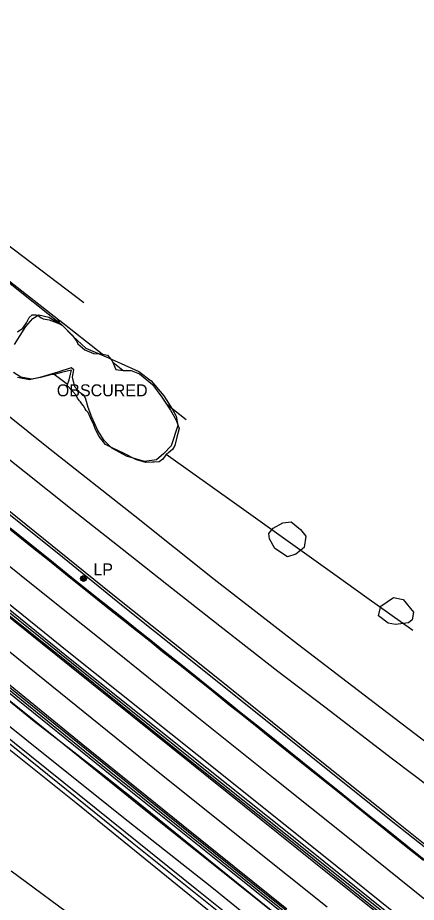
# Model space of a CAD drawing. Extents: x 368532 to 392481, y 10654822 to 10676899.
# Drawn here: x 380004 to 380170.4, y 10659071.4 to 10659440.6 of the extents above; entities that cross this region are included whole.
import ezdxf

# ---------------------------------------------------------------- set-up
doc = ezdxf.new("R2010")
doc.units = 0
for name, color, linetype in [('p_dtm obscured area', 7, 'Continuous'), ('p_dtm retaining wall', 7, 'Continuous'), ('p_dtm sidewalk', 7, 'Continuous'), ('p_railroad rr control', 7, 'Continuous'), ('p_road - paved curb', 7, 'Continuous'), ('p_road conc barrier', 7, 'Continuous'), ('p_road dirt road', 7, 'Continuous'), ('p_road paint stripe', 7, 'Continuous'), ('p_structure fence', 7, 'Continuous'), ('p_structure unidentified', 7, 'Continuous'), ('p_structure wall', 7, 'Continuous'), ('p_utility general pole', 7, 'Continuous'), ('p_veg woods', 7, 'Continuous')]:
    doc.layers.add(name, color=color, linetype=linetype)

msp = doc.modelspace()

# ---------------------------------------------------------------- linework, layer by layer
at = {"layer": 'p_dtm obscured area'}
msp.add_lwpolyline([(380003.9, 10659309.42), (380006.21, 10659311), (380007.68, 10659313.15), (380008.76, 10659315.44), (380010.11, 10659316.61), (380011.54, 10659316.5), (380012.48, 10659316.24), (380013.85, 10659315.31), (380014.65, 10659314.9), (380017.07, 10659314.49), (380022.3, 10659312.48), (380026.76, 10659308.06), (380028.69, 10659305.43), (380029.08, 10659304.42), (380032.07, 10659301.99), (380035.6, 10659300.46), (380038.86, 10659300.22), (380041.52, 10659299.67), (380043.38, 10659297.39), (380044.98, 10659293.77), (380048.01, 10659293.36), (380051.4, 10659293.33), (380054.9, 10659291.95), (380060.2, 10659287.46), (380064.15, 10659282.13), (380067.83, 10659276.72), (380070.15, 10659272.54), (380071.35, 10659269.17), (380070.41, 10659265.56), (380069.53, 10659261.97), (380068.56, 10659260.32), (380066.97, 10659258.91), (380066.03, 10659258.35), (380065.8, 10659258.06), (380064.62, 10659256.38), (380063.07, 10659255.16), (380060.96, 10659255.03), (380060.25, 10659255.01), (380057.43, 10659254.94), (380053.58, 10659256.02), (380048.12, 10659258.86), (380043.76, 10659260.9), (380040.67, 10659262.47), (380038.02, 10659265.83), (380036.42, 10659268.69), (380035.75, 10659270.63), (380034.43, 10659273.58), (380033.39, 10659275.83), (380032.54, 10659276.69), (380032.1, 10659277.38), (380031.41, 10659278.63), (380031.36, 10659278.76), (380030.83, 10659279.47), (380030.17, 10659280.24), (380029.74, 10659280.65), (380028.93, 10659281.82), (380028.4, 10659283.07), (380026.82, 10659284.66), (380024.59, 10659287.1), (380024.72, 10659287.44), (380025.55, 10659289.44), (380026.04, 10659291.76), (380026.42, 10659293.47), (380022.23, 10659292.42), (380019.16, 10659291.63), (380018.28, 10659291.61), (380013.57, 10659290.38), (380009.88, 10659289.76), (380005.29, 10659290.55), (380002.2, 10659292.5)], dxfattribs=at)
at = {"layer": 'p_dtm retaining wall'}
for p, q in [((380024.72, 10659287.44), (380019.16, 10659291.63)), ((380066.03, 10659258.35), (380067, 10659257.64)), ((380067, 10659257.64), (380094.51, 10659238.03)), ((380094.51, 10659238.03), (380109.11, 10659227.62)), ((380109.11, 10659227.62), (380136.42, 10659208.16)), ((380136.42, 10659208.16), (380149.79, 10659198.63)), ((380149.79, 10659198.63), (380168.95, 10659184.97)), ((379972.88, 10659177.76), (380010.92, 10659146.96)), ((380010.92, 10659146.96), (380026.16, 10659135.07)), ((380026.16, 10659135.07), (380041.32, 10659123.24)), ((380041.32, 10659123.24), (380052.12, 10659114.81)), ((380052.12, 10659114.81), (380084.53, 10659088.47)), ((380084.53, 10659088.47), (380133.86, 10659048.76))]:
    msp.add_line(p, q, dxfattribs=at)
at = {"layer": 'p_dtm sidewalk'}
for p, q in [((380020.43, 10659217.2), (379986.54, 10659244.35)), ((380048.04, 10659194.88), (380020.43, 10659217.2)), ((380086.6, 10659164.09), (380048.04, 10659194.88)), ((379965.55, 10659186.98), (380004.03, 10659155.88)), ((380124.3, 10659133.86), (380086.6, 10659164.09)), ((380004.03, 10659155.88), (380049.88, 10659118.84)), ((380159.15, 10659105.98), (380124.3, 10659133.86)), ((380049.88, 10659118.84), (380092.25, 10659084.87)), ((380191.31, 10659080.51), (380159.15, 10659105.98)), ((380092.25, 10659084.87), (380135.23, 10659050.48))]:
    msp.add_line(p, q, dxfattribs=at)
at = {"layer": 'p_railroad rr control'}
for points in [[(380031.65, 10659321.51), (379994.98, 10659349.29), (379961.61, 10659374.9), (379923.84, 10659403.98), (379885.83, 10659432.99), (379850.89, 10659459.72), (379817.07, 10659485.91), (379781.97, 10659514.51), (379763.8, 10659529.78), (379746.44, 10659544.62), (379721.67, 10659567.15), (379695.43, 10659591.4), (379678.11, 10659608.03), (379656.11, 10659629.71), (379630.45, 10659654.81), (379614.94, 10659670.07)], [(379982.8, 10659288.36), (380016.9, 10659261), (380052.84, 10659232.61), (380085.94, 10659206.26), (380120.72, 10659179.3), (380153.32, 10659154.27), (380191.45, 10659125.29), (380231.37, 10659095.21), (380261.57, 10659072.75), (380294.45, 10659048.57), (380330.85, 10659022.17), (380360.99, 10659000.26)], [(380347.38, 10658976.44), (380320.5, 10658997.04), (380307.32, 10659007.82), (380293.12, 10659020.18), (380275.57, 10659035.91), (380257.07, 10659052.87), (380239.39, 10659068.32), (380225.36, 10659080.48), (380211.07, 10659092.38), (380190.43, 10659108.38), (380160.49, 10659131.03), (380132.22, 10659152.81), (380112.56, 10659167.73), (380088.41, 10659186.61), (380066.31, 10659204.03), (380047.58, 10659218.72), (380026.77, 10659235.12), (380006.83, 10659250.97), (379987.69, 10659266.12), (379971.34, 10659279.52)]]:
    msp.add_lwpolyline(points, dxfattribs=at)
at = {"layer": 'p_road - paved curb'}
for p, q in [((380010.89, 10659219.06), (380000.68, 10659227.28)), ((380011.11, 10659219.33), (380000.9, 10659227.55)), ((380016.5, 10659214.61), (380010.89, 10659219.06)), ((380016.72, 10659214.88), (380011.11, 10659219.33)), ((380023.61, 10659172.45), (379971.64, 10659213.83)), ((379977.66, 10659211.92), (380025.93, 10659173.01)), ((380026.26, 10659206.65), (380016.5, 10659214.61)), ((380026.48, 10659206.92), (380016.72, 10659214.88)), ((380037.43, 10659197.77), (380026.26, 10659206.65)), ((380037.65, 10659198.04), (380026.48, 10659206.92)), ((380042.47, 10659193.73), (380037.43, 10659197.77)), ((380042.69, 10659194), (380037.65, 10659198.04)), ((380048.29, 10659189.07), (380042.47, 10659193.73)), ((380048.51, 10659189.34), (380042.69, 10659194)), ((379962.31, 10659192.11), (380009.44, 10659153.87)), ((380053.89, 10659185.06), (380048.51, 10659189.34)), ((380053.67, 10659184.79), (380048.29, 10659189.07)), ((380059.37, 10659180.3), (380053.67, 10659184.79)), ((380059.59, 10659180.57), (380053.89, 10659185.06)), ((380064.58, 10659176.08), (380059.37, 10659180.3)), ((380064.8, 10659176.35), (380059.59, 10659180.57)), ((380071.94, 10659170.27), (380064.58, 10659176.08)), ((380072.16, 10659170.54), (380064.8, 10659176.35)), ((380071.41, 10659134.08), (380023.61, 10659172.45)), ((380025.93, 10659173.01), (380074.7, 10659134.05)), ((380077.43, 10659165.82), (380071.94, 10659170.27)), ((380077.65, 10659166.09), (380072.16, 10659170.54)), ((380084.78, 10659159.95), (380077.43, 10659165.82)), ((380085, 10659160.22), (380077.65, 10659166.09)), ((380092.28, 10659153.96), (380084.78, 10659159.95)), ((380092.5, 10659154.23), (380085, 10659160.22)), ((380009.44, 10659153.87), (380058.82, 10659114.05)), ((380097.12, 10659150.08), (380092.28, 10659153.96)), ((380097.34, 10659150.35), (380092.5, 10659154.23)), ((380104.67, 10659144), (380097.12, 10659150.08)), ((380104.89, 10659144.27), (380097.34, 10659150.35)), ((380109.51, 10659140.15), (380104.67, 10659144)), ((380109.73, 10659140.42), (380104.89, 10659144.27)), ((380116.25, 10659134.71), (380109.51, 10659140.15)), ((380116.47, 10659134.98), (380109.73, 10659140.42)), ((380120.68, 10659094.74), (380071.41, 10659134.08)), ((380074.7, 10659134.05), (380125.35, 10659093.69)), ((380122.69, 10659129.55), (380116.25, 10659134.71)), ((380122.91, 10659129.82), (380116.47, 10659134.98)), ((380139.61, 10659115.99), (380122.69, 10659129.55)), ((380139.83, 10659116.26), (380122.91, 10659129.82)), ((380149.96, 10659107.66), (380139.61, 10659115.99)), ((380150.18, 10659107.93), (380139.83, 10659116.26)), ((380058.82, 10659114.05), (380106.51, 10659075.79)), ((380158.69, 10659101.12), (380150.18, 10659107.93)), ((380158.47, 10659100.85), (380149.96, 10659107.66)), ((380166.27, 10659094.58), (380158.47, 10659100.85)), ((380166.49, 10659094.85), (380158.69, 10659101.12)), ((380188.89, 10659040.08), (380120.68, 10659094.74)), ((380125.35, 10659093.69), (380171.88, 10659056.4)), ((380173.4, 10659088.87), (380166.27, 10659094.58)), ((380173.62, 10659089.14), (380166.49, 10659094.85)), ((380106.51, 10659075.79), (380156.01, 10659036.18))]:
    msp.add_line(p, q, dxfattribs=at)
msp.add_lwpolyline([(380173.31, 10659088.75), (380166.18, 10659094.46), (380158.38, 10659100.73), (380149.87, 10659107.54), (380139.52, 10659115.87), (380122.6, 10659129.43), (380116.16, 10659134.59), (380109.42, 10659140.03), (380104.58, 10659143.88), (380097.03, 10659149.96), (380092.19, 10659153.84), (380084.69, 10659159.83), (380077.34, 10659165.7), (380071.85, 10659170.15), (380064.49, 10659175.96), (380059.28, 10659180.18), (380053.58, 10659184.67), (380048.2, 10659188.95), (380042.38, 10659193.61), (380037.34, 10659197.65), (380026.17, 10659206.53), (380016.41, 10659214.49), (380010.8, 10659218.94), (380000.59, 10659227.16)], dxfattribs=at)
at = {"layer": 'p_road conc barrier'}
for p, q in [((379996.75, 10659237.79), (380043.04, 10659200.37)), ((380030.82, 10659167.77), (379981.51, 10659207.38)), ((380043.04, 10659200.37), (380086.14, 10659165.99)), ((380006.33, 10659155.19), (379965.42, 10659188.13)), ((380079.49, 10659128.73), (380030.82, 10659167.77)), ((380086.14, 10659165.99), (380122.51, 10659136.74)), ((380039.42, 10659128.38), (380006.33, 10659155.19)), ((380122.51, 10659136.74), (380161.56, 10659105.53)), ((380089.18, 10659088.35), (380039.42, 10659128.38)), ((380126.08, 10659091.52), (380079.49, 10659128.73)), ((380161.56, 10659105.53), (380198.67, 10659075.73)), ((380171.55, 10659055.3), (380126.08, 10659091.52)), ((380122.31, 10659061.87), (380089.18, 10659088.35))]:
    msp.add_line(p, q, dxfattribs=at)
at = {"layer": 'p_road dirt road'}
msp.add_line((380001.32, 10659084.48), (380032.48, 10659061.46), dxfattribs=at)
at = {"layer": 'p_road paint stripe'}
for p, q in [((380015.31, 10659199.72), (379983.71, 10659225.04)), ((379970, 10659220.34), (380025.41, 10659175.69)), ((380026.29, 10659169.55), (379977.66, 10659208.42)), ((380047.04, 10659174.31), (380015.31, 10659199.72)), ((379980.81, 10659192.06), (380011.74, 10659166.95)), ((379982.72, 10659176.7), (380030.53, 10659137.8)), ((380025.41, 10659175.69), (380078.88, 10659133.02)), ((380078.75, 10659148.74), (380047.04, 10659174.31)), ((380011.74, 10659166.95), (380064.78, 10659124.18)), ((380076.54, 10659129.1), (380026.29, 10659169.55)), ((380110.76, 10659123.21), (380078.75, 10659148.74)), ((380030.53, 10659137.8), (380073.04, 10659103.48)), ((380078.88, 10659133.02), (380131.6, 10659090.94)), ((380127.66, 10659088.12), (380076.54, 10659129.1)), ((380064.78, 10659124.18), (380100.12, 10659095.95)), ((380142.47, 10659097.84), (380110.76, 10659123.21)), ((380073.04, 10659103.48), (380116.28, 10659068.67)), ((380173.92, 10659072.54), (380142.47, 10659097.84)), ((380100.12, 10659095.95), (380133.1, 10659069.53)), ((380131.6, 10659090.94), (380181.11, 10659051.15)), ((380172.04, 10659052.56), (380127.66, 10659088.12))]:
    msp.add_line(p, q, dxfattribs=at)
at = {"layer": 'p_structure fence'}
for p, q in [((380022.2, 10659312.52), (379999.45, 10659330.59)), ((380021.16, 10659314.34), (380000.59, 10659330.46)), ((380039.29, 10659300.13), (380021.59, 10659314)), ((380047.9, 10659293.38), (380043.7, 10659296.67)), ((380074.28, 10659272.7), (380066.32, 10659278.94)), ((380010.28, 10659147.65), (379960.94, 10659187.23)), ((380004.92, 10659133.95), (379942.51, 10659183.89)), ((379964.43, 10659173.85), (380006.92, 10659139.66)), ((380056.75, 10659110.12), (380010.28, 10659147.65)), ((380006.92, 10659139.66), (380047.53, 10659107.33)), ((380051.84, 10659096.18), (380004.92, 10659133.95)), ((380111.73, 10659066.28), (380056.75, 10659110.12)), ((380047.53, 10659107.33), (380084.98, 10659077.68)), ((380107.57, 10659051.6), (380051.84, 10659096.18)), ((380084.98, 10659077.68), (380117.72, 10659051.3))]:
    msp.add_line(p, q, dxfattribs=at)
at = {"layer": 'p_structure unidentified'}
msp.add_circle((380021.22, 10659313.97), 0.375, dxfattribs=at)
at = {"layer": 'p_structure wall'}
for p, q in [((379993.99, 10659144.78), (380036.8, 10659110.54)), ((380028.31, 10659112.81), (379993.23, 10659140.86)), ((380063.88, 10659083.91), (380028.31, 10659112.81)), ((380036.8, 10659110.54), (380078.71, 10659076.69)), ((380108.22, 10659048.08), (380063.88, 10659083.91)), ((380078.71, 10659076.69), (380115.13, 10659047.76))]:
    msp.add_line(p, q, dxfattribs=at)
at = {"layer": 'p_utility general pole'}
for radius in [1.19, 0.901, 0.608, 0.337, 0.12]:
    msp.add_circle((380031.47, 10659206.51), radius, dxfattribs=at)
at = {"layer": 'p_veg woods'}
msp.add_lwpolyline([(380002.7, 10659304.12), (380007.4, 10659311.65), (380010.35, 10659315.03), (380012.8, 10659316.52), (380017.05, 10659315.62), (380022.58, 10659312.21), (380027.05, 10659307.58), (380032.38, 10659302.63), (380040.88, 10659299.07), (380047.15, 10659296.29), (380054.6, 10659292.96), (380059.68, 10659288.98), (380065, 10659282.8), (380068.68, 10659277.01), (380070.19, 10659274.19), (380070.85, 10659270.42), (380068.1, 10659261.85), (380064.94, 10659258.62), (380061.91, 10659256.1), (380056.95, 10659255.37), (380049.35, 10659257.59), (380043.24, 10659260.85), (380040.13, 10659264.16), (380037.41, 10659268.3), (380035.01, 10659273.9), (380033.47, 10659277.9), (380032.48, 10659281.29), (380031.71, 10659282.92), (380030.07, 10659283.98), (380027.84, 10659286.49), (380026.82, 10659290.56), (380027.39, 10659293.66), (380026.34, 10659294.38), (380020.77, 10659292.59), (380013.24, 10659290.4), (380008.86, 10659289.43), (380003.88, 10659290.37)], dxfattribs=at)
for points in [[(380123.59, 10659219.46), (380120.11, 10659216.7), (380116.67, 10659215.61), (380111.38, 10659219.03), (380109.1, 10659223.09), (380108.8, 10659225.33), (380110.64, 10659227.46), (380114.71, 10659229.78), (380118.2, 10659230.16), (380122.03, 10659227), (380124.26, 10659224.2)], [(380161.65, 10659187.24), (380158.59, 10659187.86), (380154.6, 10659190.89), (380155.62, 10659195.01), (380160.85, 10659198.51), (380164.86, 10659197.67), (380169.19, 10659192.46), (380168.66, 10659189.25), (380167.16, 10659187.99)]]:
    msp.add_lwpolyline(points, close=True, dxfattribs=at)

# ---------------------------------------------------------------- texts
at = {"layer": 'p_dtm obscured area'}
msp.add_text(' OBSCURED', height=5, dxfattribs=at).set_placement((380018.47, 10659282.54))
at = {"layer": 'p_utility general pole'}
msp.add_text('LP', height=5, dxfattribs=at).set_placement((380035.59, 10659207.8))

doc.saveas('drawing.dxf')
